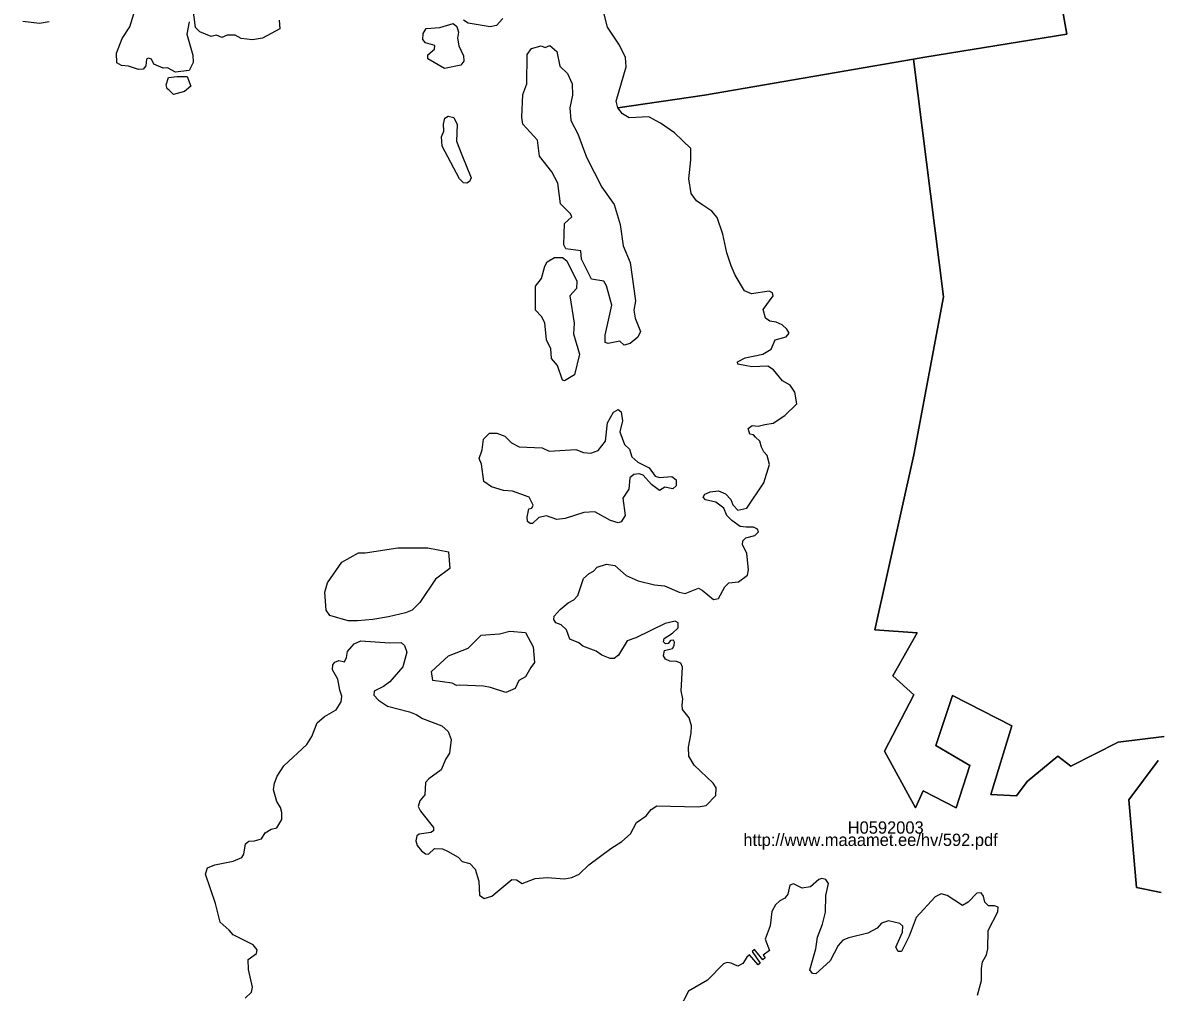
# Model space of a CAD drawing. Extents: x 369010 to 739155, y 6377141 to 6634081.
# Drawn here: x 419493 to 421797, y 6455665 to 6457634 of the extents above; entities that cross this region are included whole.
import ezdxf

# ---------------------------------------------------------------- set-up
doc = ezdxf.new("R2010")
doc.units = 0
for name, color, linetype in [('H_LINK', 7, 'Continuous'), ('H_PIIR', 7, 'Continuous'), ('H_TUNNUS', 7, 'Continuous')]:
    doc.layers.add(name, color=color, linetype=linetype)

msp = doc.modelspace()

# ---------------------------------------------------------------- linework, layer by layer
at = {"layer": 'H_PIIR'}
for points in [[(421496.24, 6458271.9247), (421613.47, 6457611.1747), (421324.53, 6457564.2446), (421301.6992, 6457560.2966), (420877.17, 6457486.8846), (420701.6501, 6457461.5246), (420697.78, 6457474.9346), (420718.2199, 6457544.5546), (420717.35, 6457563.2647), (420705.17, 6457588.5046), (420680.8101, 6457625.0547), (420673.41, 6457651.1647)], [(421811.0499, 6456184.61), (421717.6601, 6456173.12), (421621.1999, 6456124.3101), (421595.1799, 6456144.4099), (421532.4101, 6456092.72), (421510.9699, 6456064.01), (421458.92, 6456066.88), (421501.7899, 6456206.1399), (421380.84, 6456267.8799), (421347.1499, 6456165.94), (421416.05, 6456125.74), (421388.49, 6456039.6), (421321.1299, 6456074.0601), (421305.82, 6456039.6), (421243.05, 6456154.46), (421302.7499, 6456269.31), (421259.5701, 6456307.36), (421309.44, 6456394.67), (421222.99, 6456400.9), (421302.7901, 6456756.38), (421362.65, 6457077.56), (421301.6992, 6457560.2966), (421324.53, 6457564.2446), (421613.47, 6457611.1747), (421496.24, 6458271.9247)], [(420013.63, 6457639.4247), (420015.37, 6457621.5847), (419980.13, 6457602.8746), (419959.4699, 6457599.3946), (419936.4199, 6457602.0047), (419924.23, 6457608.5247), (419908.1399, 6457608.9647), (419897.2601, 6457604.1746), (419886.3801, 6457608.5247), (419875.51, 6457606.3546), (419852.45, 6457615.9247), (419844.1801, 6457624.6247), (419838.3099, 6457666.4046)], [(419830.9201, 6457635.9446), (419826.13, 6457611.1446), (419838.3099, 6457568.0647), (419839.18, 6457553.2746), (419830.9201, 6457536.7347), (419803.07, 6457533.6946), (419786.9799, 6457542.3946), (419778.2799, 6457541.9547), (419759.57, 6457549.7946), (419754.35, 6457559.7946), (419748.2599, 6457561.9746), (419744.3401, 6457559.7946), (419743.04, 6457546.3146), (419737.82, 6457539.7847), (419728.2401, 6457538.9146), (419707.8, 6457545.8746), (419693.44, 6457547.1847), (419684.2999, 6457552.4047), (419683.43, 6457572.4146), (419694.7401, 6457602.0047), (419710.8399, 6457625.9346), (419718.67, 6457652.0446)], [(420468.27, 6457642.9047), (420455.2201, 6457628.5447), (420442.17, 6457625.9346), (420397.36, 6457633.3247), (420388.2199, 6457639.4247)], [(419546.61, 6457635.9446), (419527.03, 6457632.4646), (419493.1, 6457636.3746)], [(419944.6601, 6455653.0747), (419957.45, 6455665.0447), (419959.89, 6455675.3847), (419951.73, 6455711.2947), (419950.65, 6455731.1446), (419968.05, 6455743.6647), (419969.14, 6455751.2846), (419961.2499, 6455761.3446), (419920.72, 6455781.4746), (419912.2901, 6455791.2746), (419894.07, 6455807.3246), (419884.27, 6455844.8646), (419864.4101, 6455904.4447), (419868.22, 6455917.4946), (419882.9101, 6455923.7546), (419920.18, 6455930.8246), (419938.1299, 6455938.4446), (419941.94, 6455945.5147), (419945.47, 6455966.4646), (419952.5499, 6455971.9046), (419963.43, 6455972.1747), (419978.1201, 6455976.2646), (419985.73, 6455988.5046), (419997.42, 6455995.8547), (420009.39, 6455999.1247), (420019.4599, 6456015.9847), (420019.4599, 6456029.8647), (420016.7401, 6456040.1947), (420009.39, 6456052.4446), (420002.05, 6456075.8347), (420004.22, 6456089.7147), (420009.94, 6456103.5847), (420022.9899, 6456124.8046), (420070.3199, 6456168.3347), (420080.1099, 6456184.6546), (420090.72, 6456211.8546), (420105.96, 6456225.1846), (420129.89, 6456238.2446), (420139.41, 6456254.5646), (420141.3201, 6456266.5346), (420137.2399, 6456278.5047), (420132.88, 6456300.5446), (420122, 6456319.5846), (420122.55, 6456329.6446), (420126.63, 6456335.0947), (420134.79, 6456338.6246), (420146.21, 6456336.1747), (420150.29, 6456344.6146), (420152.7399, 6456356.8547), (420166.0699, 6456372.6346), (420179.4001, 6456378.8847), (420237.7401, 6456374.8147), (420261.4101, 6456375.0846), (420268.2099, 6456369.1047), (420273.1, 6456355.7747), (420265.21, 6456325.5746), (420238.8301, 6456295.1047), (420226.0199, 6456286.1846), (420206.4299, 6456276.6547), (420206.16, 6456268.4946), (420215.41, 6456257.8846), (420233.91, 6456245.6347), (420278.26, 6456234.4746), (420291.8699, 6456228.7647), (420304.6501, 6456220.6046), (420344.11, 6456205.9046), (420356.89, 6456194.7547), (420363.4199, 6456178.1547), (420359.8899, 6456150.3947), (420352.0001, 6456139.2446), (420342.47, 6456116.9247), (420317.71, 6456098.1546), (420310.64, 6456090.8046), (420309.8201, 6456065.7646), (420299.76, 6456053.5247), (420296.22, 6456042.3647), (420300.5801, 6456032.8446), (420327.51, 6455999.6447), (420327.24, 6455992.8347), (420321.7999, 6455989.5746), (420297.86, 6455985.7646), (420293.23, 6455982.7746), (420291.05, 6455972.7047), (420294.3201, 6455962.9047), (420303.03, 6455952.0246), (420310.64, 6455945.7646), (420316.9, 6455945.4947), (420329.15, 6455956.6446), (420345.74, 6455956.3747), (420355.81, 6455951.4746), (420377.3101, 6455938.9546), (420385.4701, 6455930.7946), (420400.9801, 6455926.1646), (420411.8599, 6455915.0047), (420418.9401, 6455890.7947), (420420.84, 6455862.2146), (420429.8201, 6455855.1446), (420445.6, 6455859.7646), (420486.4101, 6455893.7846), (420495.94, 6455892.9647), (420507.37, 6455885.8946), (420533.7601, 6455895.9647), (420557.9701, 6455897.8646), (420593.0699, 6455895.4147), (420607.76, 6455898.1347), (420623.27, 6455904.9446), (420642.86, 6455923.7147), (420687.49, 6455956.6446), (420709.5199, 6455970.7947), (420727.4799, 6455986.5747), (420739.18, 6456009.4346), (420759.3201, 6456023.0346), (420769.1201, 6456036.1047), (420780.82, 6456043.4446), (420864.62, 6456041.5446), (420880.67, 6456044.2647), (420900.26, 6456064.4047), (420900.81, 6456080.1846), (420895.3599, 6456089.4346), (420856.46, 6456126.4446), (420845.8401, 6456144.6847), (420845.02, 6456162.9146), (420850.4701, 6456191.2147), (420850.74, 6456205.9146), (420846.11, 6456221.9647), (420833.0499, 6456239.1147), (420831.9601, 6456247.8147), (420833.32, 6456261.1547), (420830.3301, 6456276.9346), (420832.78, 6456325.1047), (420829.25, 6456333.2747), (420820.81, 6456336.5346), (420807.2101, 6456337.0746), (420797.9601, 6456341.7046), (420794.4199, 6456348.5046), (420796.32, 6456358.8446), (420812.65, 6456363.2047), (420815.9101, 6456368.9147), (420816.4601, 6456375.7246), (420814.5499, 6456379.8046), (420808.57, 6456379.2546), (420803.4, 6456372.9947), (420797.9601, 6456372.4547), (420794.15, 6456376.8046), (420795.5099, 6456383.6146), (420812.65, 6456394.4947), (420824.08, 6456404.8347), (420823.7999, 6456414.9046), (420818.0899, 6456418.7147), (420797.68, 6456414.0947), (420738.1, 6456384.7047), (420720.4, 6456378.9846), (420702.7201, 6456349.5946), (420693.74, 6456343.0647), (420685.85, 6456343.0647), (420668.98, 6456349.8646), (420657.28, 6456357.4847), (420630.6201, 6456367.5546), (420622.4599, 6456374.6246), (420604.23, 6456381.9746), (420597.42, 6456401.0246), (420586.54, 6456411.3546), (420575.38, 6456415.4446), (420571.3, 6456421.6946), (420572.12, 6456428.5047), (420584.63, 6456442.3847), (420600.96, 6456455.7147), (420612.1099, 6456462.2446), (420620.2801, 6456470.9546), (420631.6999, 6456504.9646), (420643.4, 6456515.5847), (420652.11, 6456519.9346), (420659.73, 6456528.3747), (420678.5001, 6456534.6247), (420695.0999, 6456531.9046), (420718.5, 6456511.2346), (420742.71, 6456500.6247), (420776.18, 6456492.4547), (420796.31, 6456490.2847), (420825.7001, 6456477.4947), (420838.2099, 6456474.7746), (420865.15, 6456485.6647), (420873.04, 6456481.3046), (420895.62, 6456462.8046), (420905.6899, 6456464.9746), (420918.4799, 6456488.6546), (420926.91, 6456496.5447), (420946.5, 6456498.7246), (420964.7301, 6456512.3246), (420966.64, 6456522.6646), (420963.37, 6456555.8647), (420954.67, 6456574.1046), (420955.4801, 6456581.9947), (420961.47, 6456587.9746), (420979.7001, 6456592.8747), (420986.77, 6456599.9547), (420984.8701, 6456605.6647), (420976.98, 6456609.2046), (420961.7399, 6456609.2046), (420950.04, 6456611.1046), (420933.17, 6456622.8147), (420922.83, 6456633.4247), (420916.8501, 6456648.3947), (420900.5199, 6456660.0946), (420879.44, 6456664.7146), (420874.5399, 6456670.4246), (420877.8, 6456676.6847), (420888.69, 6456681.3147), (420905.56, 6456683.2146), (420919.98, 6456676.9646), (420930.5899, 6456665.8046), (420934.6701, 6456654.9146), (420945.28, 6456643.7647), (420963.5101, 6456648.3847), (420998.0599, 6456699.5447), (421009.1787, 6456737.1344), (421004.8131, 6456755.3906), (420997.6693, 6456762.5344), (420993.3374, 6456771.8913), (420990.1287, 6456783.9657), (420980.8117, 6456792.1399), (420976.6349, 6456797.0626), (420969.4911, 6456798.6501), (420966.3161, 6456810.1595), (420974.2537, 6456815.7158), (420986.6453, 6456814.9428), (421000.0506, 6456818.097), (421017.1162, 6456820.8751), (421040.5319, 6456836.3533), (421064.72, 6456859.8346), (421060.9099, 6456884.0446), (421051.6599, 6456898.1947), (421035.88, 6456906.9047), (421017.6499, 6456929.2247), (421006.2201, 6456936.5646), (420973.44, 6456935.4746), (420944.87, 6456940.3747), (420944.6, 6456945.2746), (420959.84, 6456953.7146), (420996.02, 6456960.7846), (421012.6201, 6456971.1246), (421020.78, 6456990.1746), (421043.36, 6456996.4346), (421049.3499, 6457003.7847), (421044.72, 6457011.9546), (421035.2, 6457020.6546), (421023.23, 6457025.8246), (421010.44, 6457028.2746), (421001.19, 6457033.9946), (420996.2899, 6457051.4046), (421016.7001, 6457079.7046), (421015.3399, 6457085.6947), (421008.5401, 6457088.6846), (420973.16, 6457083.2447), (420958.47, 6457089.5046), (420939.7, 6457121.6146), (420931.54, 6457140.1146), (420922.82, 6457166.5147), (420914.66, 6457204.8846), (420903.23, 6457238.6247), (420892.35, 6457251.1447), (420874.39, 6457263.3847), (420861.06, 6457272.3646), (420850.18, 6457287.0647), (420845.96, 6457316.7246), (420849.39, 6457355.7147), (420849.39, 6457378.3446), (420816.3299, 6457410.5447), (420788.0499, 6457430.1247), (420764.3399, 6457443.1746), (420724.32, 6457440.9947), (420711.2599, 6457448.8346), (420701.6501, 6457461.5246), (420877.17, 6457486.8846), (421301.7001, 6457560.2899), (421362.65, 6457077.56), (421302.7901, 6456756.38), (421222.99, 6456400.9), (421309.44, 6456394.67), (421259.5701, 6456307.36), (421302.7499, 6456269.31), (421243.05, 6456154.46), (421305.82, 6456039.6), (421321.1299, 6456074.0601), (421388.49, 6456039.6), (421416.05, 6456125.74), (421347.1499, 6456165.94), (421380.84, 6456267.8799), (421501.7899, 6456206.1399), (421458.92, 6456066.88), (421510.9699, 6456064.01), (421532.4101, 6456092.72), (421595.1799, 6456144.4099), (421621.1999, 6456124.3101), (421717.6601, 6456173.12), (421811.0499, 6456184.61)], [(421804.61, 6455867.6), (421754.4, 6455877.3701), (421739.09, 6456055.39), (421798.8, 6456135.7901)], [(421798.8, 6456135.7901), (421739.09, 6456055.39), (421754.4, 6455877.3701), (421804.61, 6455867.6)], [(421431.9899, 6455659.0246), (421440.1501, 6455688.6747), (421440.1501, 6455712.8847), (421442.05, 6455726.7647), (421449.9401, 6455740.9046), (421452.6599, 6455753.4147), (421453.2, 6455790.4147), (421473.33, 6455827.9547), (421473.6001, 6455837.4746), (421466.5299, 6455840.1946), (421454.29, 6455840.4647), (421446.68, 6455848.0847), (421444.2301, 6455860.3246), (421439.06, 6455866.5847), (421430.63, 6455866.0446), (421412.9499, 6455848.0847), (421400.98, 6455841.0147), (421370.2399, 6455861.1546), (421357.73, 6455864.6947), (421346.0299, 6455858.9747), (421307.14, 6455816.5446), (421293.26, 6455778.9946), (421277.22, 6455747.9646), (421270.4199, 6455747.4246), (421266.07, 6455756.6746), (421279.6699, 6455787.1446), (421279.94, 6455799.1146), (421274.23, 6455804.5546), (421250.8299, 6455809.9947), (421236.9599, 6455805.0946), (421227.7099, 6455794.7646), (421209.2199, 6455784.6946), (421170.32, 6455775.4447), (421158.36, 6455770.5446), (421148.6999, 6455759.6747), (421132.6601, 6455728.9246), (421103.28, 6455701.9947), (421096.48, 6455703.0847), (421091.5799, 6455710.4246), (421103.28, 6455752.8647), (421107.0899, 6455776.8046), (421116.8799, 6455802.9247), (421122.8601, 6455827.6846), (421124.09, 6455861.1446), (421129.26, 6455885.6247), (421124.09, 6455893.7946), (421115.9301, 6455895.9647), (421109.3999, 6455893.7946), (421092.54, 6455879.1047), (421075.9499, 6455876.1046), (421058.27, 6455885.3546), (421050.92, 6455882.6347), (421046.84, 6455864.1347), (421040.3201, 6455855.7046), (421030.5301, 6455850.2647), (421021.55, 6455842.6446), (421014.48, 6455829.0447), (421010.94, 6455799.6647), (421000.61, 6455773.0047), (421009.31, 6455749.8847), (420996.8, 6455740.3646), (421000.88, 6455734.6446), (420995.98, 6455730.8347), (420979.1201, 6455751.5146), (420973.9501, 6455747.7047), (420990.82, 6455724.3146), (420986.4599, 6455720.5047), (420968.7801, 6455740.9046), (420963.6201, 6455736.0047), (420955.4601, 6455723.2246), (420944.85, 6455717.7846), (420931.7901, 6455723.7546), (420923.35, 6455725.1147), (420916.01, 6455722.3946), (420883.64, 6455689.4747), (420845.2901, 6455666.8947), (420826.52, 6455631.7946)]]:
    msp.add_lwpolyline(points, dxfattribs=at)
for points in [[(420382.9784, 6457547.6294), (420349.8776, 6457541.0091), (420315.6182, 6457561.0352), (420315.6182, 6457568.9794), (420329.024, 6457580.7302), (420329.8515, 6457587.6812), (420310.8186, 6457593.3085), (420305.5226, 6457599.7631), (420306.3501, 6457612.0103), (420312.4736, 6457622.4372), (420339.9473, 6457624.5886), (420366.9244, 6457632.8639), (420374.7031, 6457626.7402), (420378.1788, 6457614.6585), (420376.0272, 6457602.4111), (420378.6752, 6457587.1848), (420388.2746, 6457567.1587), (420389.1021, 6457555.9045)], [(420563.3778, 6457587.6812), (420577.6111, 6457575.9306), (420583.7348, 6457545.8087), (420599.4577, 6457531.079), (420608.8912, 6457509.729), (420609.7189, 6457486.7238), (420604.0916, 6457461.0708), (420605.7466, 6457435.7487), (420620.1456, 6457408.7714), (420638.0199, 6457360.9409), (420668.8038, 6457300.3664), (420694.2914, 6457264.6174), (420706.5386, 6457224.5656), (420712.0002, 6457181.0379), (420726.5647, 6457147.2752), (420737.6534, 6457069.1572), (420734.0123, 6457050.4554), (420736.4948, 6457034.2359), (420747.2526, 6457007.2588), (420742.1221, 6456995.3425), (420726.7301, 6456982.5988), (420714.6484, 6456978.9576), (420705.3801, 6456987.2327), (420681.5476, 6456982.7642), (420676.086, 6456984.7502), (420675.9205, 6456999.4801), (420688.9952, 6457060.22), (420678.5685, 6457099.9411), (420672.9414, 6457109.0437), (420647.7848, 6457113.3469), (420627.9243, 6457154.0608), (420626.2693, 6457170.7767), (420595.982, 6457174.7488), (420591.679, 6457183.024), (420593.334, 6457226.2206), (420608.0637, 6457239.6264), (420605.4157, 6457246.0811), (420584.8932, 6457266.4381), (420579.7627, 6457307.9796), (420567.1844, 6457331.4811), (420542.1932, 6457363.0923), (420538.0557, 6457395.3656), (420508.5958, 6457427.97), (420506.2788, 6457442.3688), (420508.927, 6457488.3788), (420516.8711, 6457510.2254), (420517.2021, 6457569.8069), (420525.9738, 6457581.5577), (420545.5033, 6457587.1848), (420554.275, 6457583.7091)], [(419788.8151, 6457523.019), (419806.8068, 6457524.6065), (419826.9152, 6457525.1357), (419834.3235, 6457505.0273), (419821.6235, 6457494.444), (419799.3984, 6457488.094), (419789.8734, 6457497.619), (419786.6984, 6457499.7357), (419784.5817, 6457508.2024)], [(420400.3563, 6457311.6206), (420395.2256, 6457308.476), (420388.44, 6457309.1381), (420379.6683, 6457316.7513), (420344.9123, 6457383.1184), (420343.2573, 6457402.3168), (420348.388, 6457414.0676), (420347.5605, 6457428.3009), (420350.5396, 6457440.5483), (420357.1597, 6457444.0238), (420368.4139, 6457441.3758), (420375.3651, 6457427.1425), (420373.7101, 6457393.5451), (420384.9643, 6457365.7405), (420403.5009, 6457319.2339)], [(420613.5254, 6456918.8797), (420593.1685, 6456906.4669), (420588.8653, 6456908.1219), (420578.935, 6456937.9126), (420566.5223, 6456951.815), (420565.6948, 6456971.6755), (420556.4266, 6456989.7154), (420553.4474, 6457024.8022), (420546.4962, 6457037.546), (420534.58, 6457050.2899), (420534.58, 6457099.2791), (420546.8274, 6457114.5054), (420553.282, 6457139.8275), (420557.9161, 6457148.4337), (420572.977, 6457157.2054), (420589.3619, 6457157.5365), (420597.9681, 6457150.2542), (420618.1595, 6457109.3747), (420617.332, 6457094.4795), (420604.2573, 6457079.0875), (420612.8635, 6457023.6437), (420611.5394, 6457001.9626), (420623.9522, 6456961.0831)], [(420725.0751, 6456768.2711), (420730.2057, 6456752.3826), (420741.9565, 6456741.7904), (420765.2926, 6456730.205), (420777.5398, 6456713.3237), (420785.9805, 6456710.5101), (420811.4683, 6456712.1651), (420819.9089, 6456705.7105), (420819.9089, 6456693.4633), (420813.1233, 6456687.1741), (420796.7384, 6456690.4842), (420786.146, 6456683.8641), (420769.5956, 6456696.1113), (420753.0452, 6456715.4753), (420745.101, 6456718.1233), (420734.1778, 6456716.3028), (420725.5717, 6456709.5171), (420723.9165, 6456686.6775), (420711.6693, 6456668.3066), (420716.138, 6456633.2197), (420708.5247, 6456620.4759), (420702.2356, 6456618.3243), (420686.5127, 6456623.1239), (420654.5703, 6456640.833), (420632.2274, 6456639.1779), (420594.327, 6456627.2617), (420577.7766, 6456625.441), (420556.9231, 6456632.7233), (420540.8691, 6456628.9167), (420528.4563, 6456617.0004), (420523.3258, 6456617.1659), (420517.8641, 6456620.8069), (420517.2021, 6456629.7442), (420521.0087, 6456646.791), (420527.1324, 6456648.4462), (420529.4494, 6456654.4042), (420521.6707, 6456670.2926), (420487.9079, 6456682.7054), (420469.537, 6456683.8641), (420445.0424, 6456691.1462), (420429.485, 6456702.4004), (420424.8509, 6456737.8183), (420420.0513, 6456749.238), (420426.0093, 6456766.6161), (420428.492, 6456788.1315), (420441.0703, 6456800.3787), (420455.8001, 6456800.5444), (420471.8541, 6456794.2552), (420485.4254, 6456781.0149), (420501.4792, 6456772.905), (420547.9858, 6456770.5881), (420562.2191, 6456763.8024), (420616.0081, 6456767.609), (420632.0619, 6456761.3199), (420646.9573, 6456759.9958), (420661.3561, 6456765.1265), (420676.5824, 6456784.3249), (420680.389, 6456821.7287), (420692.8018, 6456843.0789), (420701.9046, 6456848.706), (420708.1936, 6456843.9064), (420711.0073, 6456825.7008), (420705.2147, 6456803.3578), (420714.8139, 6456777.2082)], [(420140.8569, 6456538.5649), (420175.2528, 6456557.0857), (420188.482, 6456557.0857), (420254.628, 6456567.6691), (420315.4823, 6456567.6691), (420357.8157, 6456559.7316), (420360.4615, 6456525.3357), (420331.3573, 6456504.169), (420299.6072, 6456456.5439), (420283.7322, 6456440.6688), (420270.503, 6456435.3772), (420236.1071, 6456427.4396), (420204.3571, 6456422.148), (420172.607, 6456419.5021), (420154.0861, 6456419.5021), (420117.0444, 6456430.0855), (420109.1069, 6456440.6688), (420106.461, 6456477.7106), (420111.7527, 6456496.2314)], [(420357.8157, 6456348.0645), (420397.5033, 6456363.9395), (420423.9617, 6456390.3979), (420461.0034, 6456393.0437), (420482.1701, 6456398.3354), (420513.9202, 6456395.6896), (420529.7952, 6456366.5854), (420532.441, 6456334.8353), (420524.5035, 6456324.2519), (420513.9202, 6456305.7311), (420500.691, 6456297.7936), (420492.7535, 6456281.9185), (420474.2326, 6456273.981), (420443.08, 6456284.05), (420428.76, 6456286.91), (420379.84, 6456288.73), (420374.12, 6456288.21), (420365.01, 6456292.64), (420326.0656, 6456297.7936), (420323.4198, 6456316.3144)]]:
    msp.add_lwpolyline(points, close=True, dxfattribs=at)

# ---------------------------------------------------------------- texts
at = {"layer": 'H_LINK'}
msp.add_text('http://www.maaamet.ee/hv/592.pdf', height=25, rotation=360, dxfattribs=at).set_placement((420956.3602, 6455961.9997))
at = {"layer": 'H_TUNNUS'}
msp.add_text('H0592003', height=25, rotation=360, dxfattribs=at).set_placement((421168.2147, 6455986.9997))

doc.saveas('drawing.dxf')
